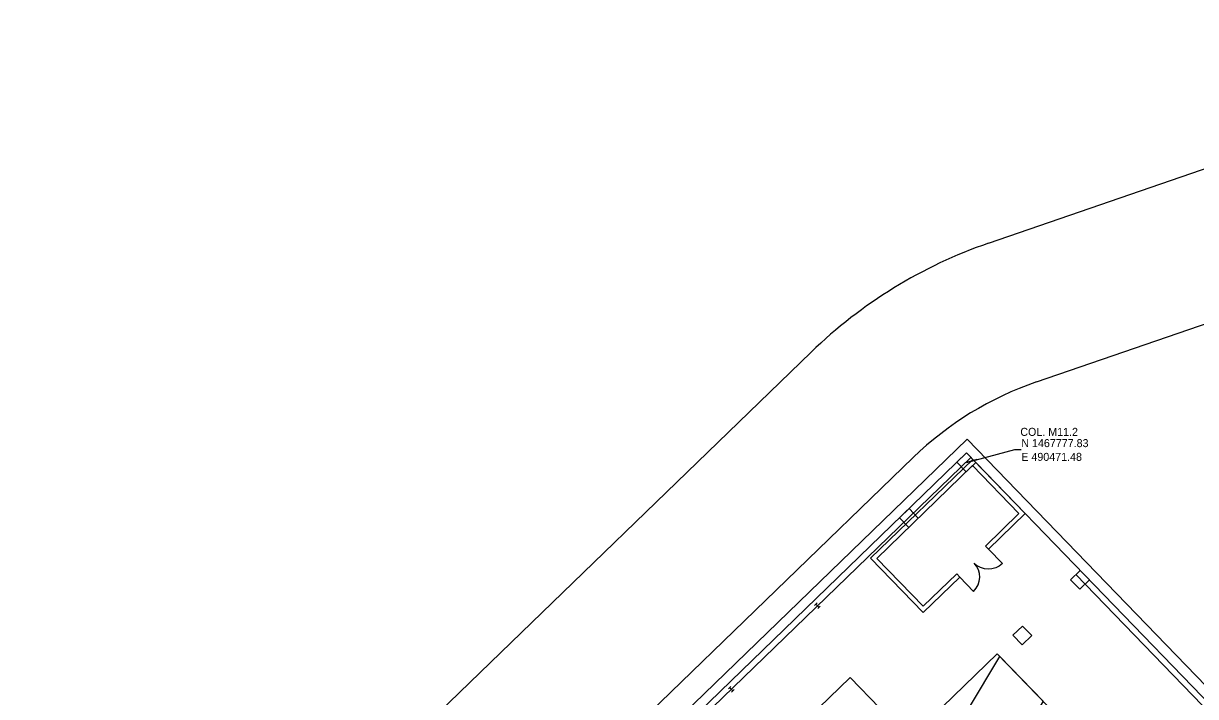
# Model space of a CAD drawing. Extents: x 468143 to 491361, y 1438528 to 1468730.
# Drawn here: x 490330 to 490505.8, y 1467742.7 to 1467843.6 of the extents above; entities that cross this region are included whole.
import ezdxf

# ---------------------------------------------------------------- set-up
doc = ezdxf.new("R2010")
doc.units = 0
doc.layers.add('Default', color=7, linetype='Continuous')
doc.layers.add('Xreference_dp', color=7, linetype='Continuous')

# ---------------------------------------------------------------- blocks, each defined once
blk = doc.blocks.new('door')
at = {"layer": 'Default'}
blk.add_line((0, 0), (0, 36), dxfattribs=at)
blk.add_arc((0, 0), 36, 90, 180, dxfattribs=at)
blk = doc.blocks.new('cable suppt')
at = {"layer": 'Default'}
for points in [[(-3.2, 4), (3.2, 4)], [(0, -4), (0, 4)], [(-3.2, -4), (3.2, -4)]]:
    blk.add_lwpolyline(points, dxfattribs=at)
blk = doc.blocks.new('cable suppt bay')
at = {"layer": 'Default'}
for p in [(227.999544, 0.999998), (443.999112, 0.999998)]:
    blk.add_blockref('cable suppt', p, dxfattribs=at)
blk = doc.blocks.new('STALL 9FT-75D')
at = {"layer": 'Default'}
for p, q in [((0, 0), (111.8, 0)), ((111.8, 0), (167.7, -208.6))]:
    blk.add_line(p, q, dxfattribs=at)
blk.add_lwpolyline([(55.9, -208.6), (0, 0)], dxfattribs=at)
blk.add_text('9FT', height=18, dxfattribs=at).set_placement((86.4, -185.9))
blk = doc.blocks.new('Col 24x24')
at = {"layer": 'Default'}
blk.add_lwpolyline([(-11.999976, -11.999976), (-11.999976, 11.999976), (11.999976, 11.999976), (11.999976, -11.999976), (-11.999976, -11.999976)], dxfattribs=at)
blk.add_lwpolyline([(-11.999976, -11.999976), (11.999976, -11.999976), (11.999976, 11.999976), (-11.999976, 11.999976)], close=True, dxfattribs=at)

msp = doc.modelspace()

# ---------------------------------------------------------------- linework, layer by layer
at = {"layer": 'Xreference_dp'}
for p, q in [((490474.8, 1467810.68), (490560.43, 1467840.19)), ((490474.8, 1467810.68), (490560.43, 1467840.19)), ((490481.97, 1467789.88), (490567.59, 1467819.39)), ((490481.97, 1467789.88), (490567.59, 1467819.39)), ((490081.81, 1467439.97), (490448.2, 1467794.36)), ((490081.81, 1467439.97), (490448.2, 1467794.36)), ((490097.76, 1467424.8), (490463.5, 1467778.55)), ((490097.76, 1467424.8), (490463.5, 1467778.55)), ((490139.28, 1467457.72), (490471.49, 1467779.24)), ((490139.28, 1467457.72), (490471.49, 1467779.24)), ((490471.49, 1467779.24), (490516.35, 1467732.9)), ((490471.49, 1467779.24), (490516.35, 1467732.9)), ((490474.79, 1467764.81), (490474.33, 1467765.29)), ((490474.79, 1467764.81), (490474.33, 1467765.29)), ((490470.48, 1467760.64), (490470.02, 1467761.12)), ((490470.48, 1467760.64), (490470.02, 1467761.12))]:
    msp.add_line(p, q, dxfattribs=at)
msp.add_lwpolyline([(490342.06, 1467246.02), (490137.16, 1467457.76), (490471.58, 1467781.33), (490516.38, 1467735.04), (490628.6, 1467843.61), (490790.28, 1467676.55), (490385, 1467284.32)], close=True, dxfattribs=at)
msp.add_lwpolyline([(490342.06, 1467246.02), (490137.16, 1467457.76), (490471.58, 1467781.33), (490516.38, 1467735.04), (490628.6, 1467843.61), (490790.28, 1467676.55), (490385, 1467284.32)], close=True, dxfattribs=at)
for points in [[(490385.72, 1467679.47), (490454.03, 1467745.57), (490462.92, 1467736.38), (490476.11, 1467749.14), (490512.08, 1467711.97), (490597.15, 1467794.31), (490608.23, 1467782.86), (490646.1, 1467819.51)], [(490385.72, 1467679.47), (490454.03, 1467745.57), (490462.92, 1467736.38), (490476.11, 1467749.14), (490512.08, 1467711.97), (490597.15, 1467794.31), (490608.23, 1467782.86), (490646.1, 1467819.51)], [(490472.13, 1467778.58), (490382.31, 1467691.65)], [(490472.13, 1467778.58), (490382.31, 1467691.65)], [(490474.79, 1467764.81), (490480.3, 1467770.14), (490472.42, 1467778.28), (490457.09, 1467763.45), (490464.97, 1467755.3), (490470.48, 1467760.64)], [(490474.79, 1467764.81), (490480.3, 1467770.14), (490472.42, 1467778.28), (490457.09, 1467763.45), (490464.97, 1467755.3), (490470.48, 1467760.64)], [(490473.02, 1467778.24), (490471.47, 1467777.83), (490478.76, 1467779.75), (490479.71, 1467779.75)], [(490473.02, 1467778.24), (490471.47, 1467777.83), (490478.76, 1467779.75), (490479.71, 1467779.75)], [(490474.33, 1467765.29), (490479.36, 1467770.16), (490472.4, 1467777.34), (490458.03, 1467763.43), (490464.99, 1467756.25), (490470.02, 1467761.12)], [(490474.33, 1467765.29), (490479.36, 1467770.16), (490472.4, 1467777.34), (490458.03, 1467763.43), (490464.99, 1467756.25), (490470.02, 1467761.12)], [(490487.87, 1467761), (490517.08, 1467730.82)], [(490487.87, 1467761), (490517.08, 1467730.82)]]:
    msp.add_lwpolyline(points, dxfattribs=at)
for radius in [72, 72, 50, 50]:
    msp.add_arc((490498.26, 1467742.61), radius, 109.016, 134.0456, dxfattribs=at)

# ---------------------------------------------------------------- block references
for name, p, xscale, yscale, rotation in [('Col 24x24', (490471.47, 1467777.83), 0.0833307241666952, 0.0833307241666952, 44.062944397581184), ('Col 24x24', (490471.47, 1467777.83), 0.0833307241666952, 0.0833307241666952, 44.062944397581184), ('Col 24x24', (490462.85, 1467769.48), 0.0833307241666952, 0.0833307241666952, 44.062944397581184), ('Col 24x24', (490462.85, 1467769.48), 0.0833307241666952, 0.0833307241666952, 44.062944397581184), ('door', (490474.79, 1467764.81), 0.0833307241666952, -0.08333072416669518, 44.062936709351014), ('door', (490474.79, 1467764.81), 0.0833307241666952, -0.08333072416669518, 44.062936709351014), ('door', (490470.48, 1467760.64), 0.08333072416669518, 0.08333072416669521, -135.93706329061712), ('door', (490470.48, 1467760.64), 0.08333072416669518, 0.08333072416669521, -135.93706329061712), ('Col 24x24', (490488.51, 1467760.22), 0.0833307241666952, 0.0833307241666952, 44.062944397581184), ('Col 24x24', (490488.51, 1467760.22), 0.0833307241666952, 0.0833307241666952, 44.062944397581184), ('cable suppt bay', (490422.61, 1467730.54), 0.08333072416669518, 0.0833307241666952, 44.06293670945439), ('cable suppt bay', (490422.61, 1467730.54), 0.08333072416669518, 0.0833307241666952, 44.06293670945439), ('Col 24x24', (490479.88, 1467751.88), 0.0833307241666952, 0.0833307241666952, 44.062944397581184), ('Col 24x24', (490479.88, 1467751.88), 0.0833307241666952, 0.0833307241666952, 44.062944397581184), ('STALL 9FT-75D', (490476.49, 1467748.75), 0.08333072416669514, 0.08333072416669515, -45.942932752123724), ('STALL 9FT-75D', (490476.49, 1467748.75), 0.08333072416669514, 0.08333072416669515, -45.942932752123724)]:
    msp.add_blockref(name, p, dxfattribs=dict(at, xscale=xscale, yscale=yscale, rotation=rotation))

# ---------------------------------------------------------------- texts
for s, p in [('COL. M11.2', (490479.56, 1467781.8)), ('COL. M11.2', (490479.56, 1467781.8)), ('N 1467777.83', (490479.71, 1467780.11)), ('N 1467777.83', (490479.71, 1467780.11)), ('E 490471.48', (490479.71, 1467778.05)), ('E 490471.48', (490479.71, 1467778.05))]:
    msp.add_text(s, height=1.2, dxfattribs=at).set_placement(p)

doc.saveas('drawing.dxf')
